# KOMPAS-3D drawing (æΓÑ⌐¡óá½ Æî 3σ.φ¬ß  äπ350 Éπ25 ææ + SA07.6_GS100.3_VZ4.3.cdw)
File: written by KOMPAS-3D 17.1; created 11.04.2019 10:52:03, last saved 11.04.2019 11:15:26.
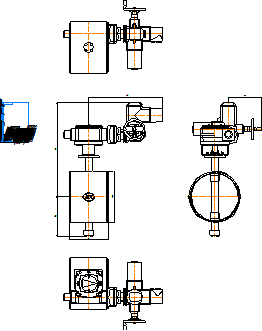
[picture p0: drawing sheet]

Sheet 1: A4, portrait

Title block, sheet 1: name: Стейнвал ТМ 3х.экс / Ду350 Ру25 СС + SA07.6_GS100.3_VZ4.3; material: Внимание! Данный продукт является объектом авторского права ООО «Торговый Дом АДЛ». / Запрещается изменение, копирование, распространение / (в том числе путем копирования на другие сайты и ресурсы в Интернете) / или любое иное использование информации и объектов без предварительного / согласия правообладателя (ООО «Торговый Дом АДЛ»).; mass: 206,87; sheets: 1; organisation: ООО "Торговый дом АДЛ"; sheet format: A4

Views: Вид 1, Проекционный вид 2, Проекционный вид 3, Проекционный вид 4
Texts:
  user
Dimensions and other numbers on the sheet: 702,8; 290,4; 549; 290; 377; 248,7; 1:1; 1; 206,87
